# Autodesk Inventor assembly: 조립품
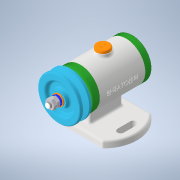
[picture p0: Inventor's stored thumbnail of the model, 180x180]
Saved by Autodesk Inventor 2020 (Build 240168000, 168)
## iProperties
Created: 2021-09
Part Number: 조립품
Document SubType Name: Assembly
Designer: Administrator
Author: Administrator
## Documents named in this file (13)
- C:\Users\Administrator\Downloads\710906V1015\조립품.iam
- C:\Users\Administrator\Downloads\710906V1015\본체.ipt
- C:\Users\Administrator\Downloads\710906V1015\축.ipt
- C:\Users\Administrator\Downloads\710906V1015\앞커버.ipt
- C:\Users\Administrator\Downloads\710906V1015\뒤커버.ipt
- C:\Users\Administrator\Downloads\710906V1015\오일 실 15x25x7.ipt
- C:\Users\Administrator\Downloads\710906V1015\베어링 15x32x9.ipt
- C:\Users\Administrator\Downloads\710906V1015\키 3x3.ipt
- C:\Users\Administrator\Downloads\710906V1015\V벨트풀리.ipt
- C:\Users\Administrator\Downloads\710906V1015\와셔 8x17.ipt
- C:\Users\Administrator\Downloads\710906V1015\스프링와셔 8.ipt
- C:\Users\Administrator\Downloads\710906V1015\너트 M8.ipt
- C:\Users\Administrator\Downloads\710906V1015\캡.ipt
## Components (1 placed, 1 different names)
1. V벨트풀리:1
